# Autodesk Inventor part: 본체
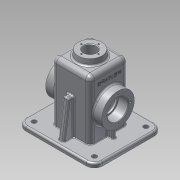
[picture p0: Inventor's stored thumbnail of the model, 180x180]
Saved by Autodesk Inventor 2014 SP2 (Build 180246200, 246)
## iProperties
Created: 2016-08
Part Number: 본체
Material: 알루미늄 6061
Document SubType Name: Modeling
Designer: user
Density: 2.71 g/cm^3
Appearance: 알루미늄 - 평지
Mass: 800.305 g
Surface Area: 911.822 cm^2
Volume: 295.316 cm^3
Author: user
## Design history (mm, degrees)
sketch "스케치1"
  geometry: L1 (-65, -57.5)-(65, -57.5); L2 (65, -57.5)-(65, 57.5); L3 (65, 57.5)-(-65, 57.5); L4 (-65, 57.5)-(-65, -57.5); L5 (-65, -57.5)-(65, 57.5); L6 (65, -57.5)-(-65, 57.5); 1 further point
  constraints: 12 end point, 2 midpoint, 2 parallel, 1 horizontal, 1 perpendicular
  dimensions: "d0" = 130 distance of L2.end L3.end; "d1" = 115 distance of L1.end L2.end
extrude "돌출1" new body sketch "스케치1" distance "d2" = 10; taper "d3" = 0 deg
sketch "스케치2"
  geometry: L1 (65, -57.5)-(-65, -57.5) reference; L2 (65, 57.5)-(65, -57.5) reference; L3 (-65, 57.5)-(65, 57.5) reference; L4 (-65, -57.5)-(-65, 57.5) reference; L5 (-60, 52.5)-(60, 52.5); L6 (60, 52.5)-(60, -52.5); L7 (60, -52.5)-(-60, -52.5); L8 (-60, -52.5)-(-60, 52.5); 1 further point
  constraints: 8 end point, 3 other
  dimensions: "d4" = 5 distance between parallel lines of L4 L8
extrude "돌출2" cut sketch "스케치2" distance "d5" = 3; taper "d6" = 0 deg
sketch "스케치3"
  geometry: L1 (32.5, 110)-(-32.5, 110); L2 (-32.5, 110)-(-32.5, 0); L3 (-32.5, 0)-(32.5, 0); L4 (32.5, 0)-(32.5, 110); 2 further points
  constraints: 8 end point, 2 parallel, 1 coincident, 1 horizontal, 1 midpoint, 1 perpendicular
  dimensions: "d7" = 65 distance of L2.end L3.end; "d8" = 110 distance of L1.end L2.end
extrude "돌출3" join sketch "스케치3" stored distance "d9" = 65; taper "d10" = 0 deg
sketch "스케치5"
  geometry: C1 r 27.5 at (-45, 32.5); 1 further point
  constraints: 1 centre point, 1 horizontal alignment
  dimensions: "d16" = 55 distance of point (10, 32.5) C1.centre; "d17" = 55 diameter of C1
extrude "돌출5" join sketch "스케치5" distance "d18" = 15; taper "d20" = 0 deg; dims "d19" = 80, "d21" = 0
sketch "스케치4"
  geometry: L1 (27.5, 105)-(-27.5, 105); L2 (-27.5, 105)-(-27.5, 0); L3 (-27.5, 0)-(27.5, 0); L4 (27.5, 0)-(27.5, 105); L5 (32.5, 110)-(-32.5, 110) reference; 2 further points
  constraints: 8 end point, 2 parallel, 1 coincident, 1 horizontal, 1 midpoint, 1 perpendicular
  dimensions: "d11" = 55 distance of L2.end L3.end; "d13" = 5 distance between parallel lines of L5 L1
extrude "돌출4" cut sketch "스케치4" stored distance "d14" = 55; taper "d15" = 0 deg
node "작업 평면1"
hole "구멍1" diameter "d24" = 30; stored, may be unused: countersink angle "d28" = 90 deg, drill point angle "d30" = 0 deg; dims "d22" = 10, "d23" = 10, "d25" = 6, "d26" = 35, "d27" = 17, "d29" = 30
hole "구멍2" diameter "d33" = 30; stored, may be unused: countersink angle "d37" = 90 deg, drill point angle "d39" = 0 deg; dims "d31" = 10, "d32" = 10, "d34" = 6, "d35" = 35, "d36" = 17, "d38" = 30
sketch "스케치6"
  geometry: C1 r 20 at (32.5, -32.5); 1 further point
  constraints: 1 centre point, 1 coincident
  dimensions: "d41" = 40 diameter of C1
extrude "돌출6" join sketch "스케치6" stored distance "d42" = 15; taper "d43" = 7 deg
hole "구멍3" diameter "d46" = 21; stored, may be unused: countersink angle "d50" = 90 deg, drill point angle "d52" = 0 deg; dims "d44" = 10, "d45" = 10, "d47" = 6, "d48" = 35, "d49" = 17, "d51" = 30
fillet "모깎기1" dims "d53" = 8
fillet "모깎기13" dims "d111" = 3
fillet "모깎기2" dims "d54" = 14
sketch "스케치7"
  geometry: L1 (-42.5, 9)-(-27.5, 9); L2 (-42.5, 9)-(-42.5, 29); L3 (-42.5, 29)-(-27.5, 29); L4 (-27.5, 29)-(-27.5, 9); 1 further point
  constraints: 8 end point, 2 perpendicular, 1 parallel, 1 vertical
  dimensions: "d142" = 15 distance of L1.start L1.end; "d143" = 20 distance of L1.start L2.end; "d144" = 9 vertical distance of L1.start point (0, 0); "d145" = 27.5 horizontal distance of L3.end point (0, 0)
extrude "돌출7" join sketch "스케치7" stored distance "d57" = 6; taper "d58" = 0 deg
sketch "스케치8"
  geometry: L1 (32.5, 70)-(32.5, 10); L2 (32.5, 10)-(49.5, 10); L3 (49.5, 10)-(41.068, 70); L4 (41.068, 70)-(32.5, 70); L5 (57.5, 10)-(57.5, 3) reference; L6 (43.5, 10)-(57.5, 10) reference; 2 further points
  constraints: 8 end point, 1 coincident, 1 parallel, 1 perpendicular, 1 point on line, 1 vertical
  dimensions: "d59" = 70 vertical distance of L3.end point (0, 0); "d61" = 8 deg angle of L3 L5; "d62" = 8 horizontal distance of L5.end L2.end
extrude "돌출8" join sketch "스케치8" stored distance "d63" = 10; taper "d64" = 0 deg
hole "구멍4" diameter "d67" = 8; stored, may be unused: countersink angle "d71" = 90 deg, drill point angle "d73" = 0 deg; dims "d65" = 10, "d66" = 10, "d68" = 6, "d69" = 35, "d70" = 17, "d72" = 30
hole "구멍5" diameter "d76" = 8; stored, may be unused: countersink angle "d80" = 90 deg, drill point angle "d82" = 0 deg; dims "d74" = 10, "d75" = 10, "d77" = 6, "d78" = 35, "d79" = 17, "d81" = 30
hole "구멍6" diameter "d85" = 8; stored, may be unused: countersink angle "d89" = 90 deg, drill point angle "d91" = 0 deg; dims "d83" = 10, "d84" = 10, "d86" = 6, "d87" = 35, "d88" = 17, "d90" = 30
hole "구멍7" diameter "d94" = 8; stored, may be unused: countersink angle "d98" = 90 deg, drill point angle "d100" = 0 deg; dims "d92" = 10, "d93" = 10, "d95" = 6, "d96" = 35, "d97" = 17, "d99" = 30
fillet "모깎기3" dims "d101" = 9
fillet "모깎기5" dims "d103" = 3
fillet "모깎기6" dims "d104" = 3
fillet "모깎기8" dims "d106" = 3
fillet "모깎기9" dims "d107" = 3
fillet "모깎기10" dims "d108" = 3
sketch "스케치9"
  geometry: 2 further points
  constraints: 1 horizontal alignment
  dimensions: "d112" = 14.5 distance of point (14.5, 0) point (0, 0)
hole "구멍8" sketch "스케치9" at (14.5, 0) diameter "d113" = 2.459; stored, may be unused: countersink angle "d117" = 90 deg, drill point angle "d119" = 118 deg; dims "d114" = 7, "d115" = 35, "d116" = 17, "d118" = 9
sketch "스케치10"
  geometry: C1 r 17.5 at (0, 0) reference; 2 further points
  constraints: 1 vertical alignment
  dimensions: "d123" = 21 distance of point (0, 21) C1.centre
hole "구멍9" sketch "스케치10" at (0, 21) diameter "d124" = 3.242; stored, may be unused: countersink angle "d128" = 90 deg, drill point angle "d130" = 118 deg; dims "d125" = 8, "d126" = 35, "d127" = 17, "d129" = 10
fillet "모깎기14" dims "d134" = 0.3
fillet "모깎기15" dims "d135" = 3
fillet "모깎기16" dims "d136" = 3
sketch "스케치11"
  geometry: L1 (0, -8)-(92, -8) reference; L2 (-18, 4.5)-(-18, 44.5) reference; 2 further points
  constraints: 1 other
  dimensions: "d137" = 32.5 distance from line of L1 point (8, 24.5); "d138" = 26 distance from line of L2 point (8, 24.5)
feature "엠보싱1" sketch "스케치11" dims "d139" = 0.5, "d140" = 0
fillet "모깎기17" dims "d146" = 3
fillet "모깎기18" dims "d147" = 1
chamfer "모따기1" distance "d148" = 1; stored, may be unused: second distance "d149" = 2, angle "d150" = 45 deg
fillet "모깎기19" dims "d151" = 3
fillet "모깎기20" dims "d152" = 3
node "솔리드1"
mirror "대칭1"
mirror "대칭2"
pattern_circular "원형 패턴1" dims angle "d121" = 360 deg
pattern_circular "원형 패턴2" dims angle "d132" = 360 deg
mirror "대칭3"
node "투영된 루프1"
